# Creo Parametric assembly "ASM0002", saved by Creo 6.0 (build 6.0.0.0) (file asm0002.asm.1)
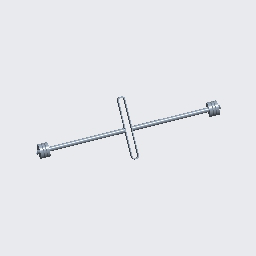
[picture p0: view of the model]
Units: millimeter Newton Second (mmNs); MM, TONNE, SECS

Created from: MMNS_ASM_DESIGN.ASM

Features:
  1. datum plane "ASM_RIGHT"
  2. datum plane "ASM_TOP"
  3. datum plane "ASM_FRONT"
  4. coordinate system
  5. component "YOKE"
  6. component "PISTON"
  7. component "PISTON"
